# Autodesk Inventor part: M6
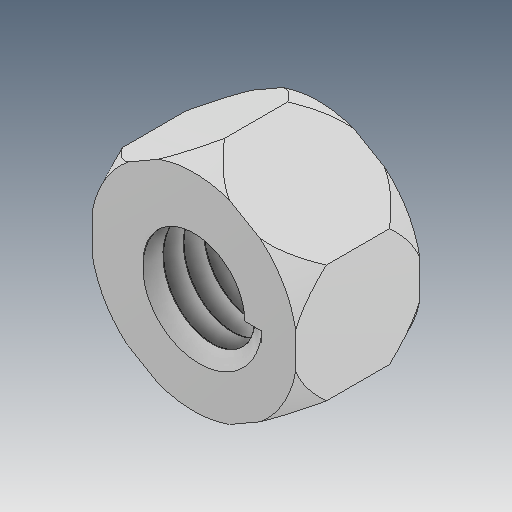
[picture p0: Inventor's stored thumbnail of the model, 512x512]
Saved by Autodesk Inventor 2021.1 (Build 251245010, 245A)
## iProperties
Created: 2021-05
Part Number: M6
Material: Ogólny
Document SubType Name: Modeling
Designer: user
Density: 1 g/cm^3
Appearance: Domyślna
Author: user
Revision Number: ÈÎºÎ
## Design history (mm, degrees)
feature "ÊäÈë1"
node "Bryła1"
